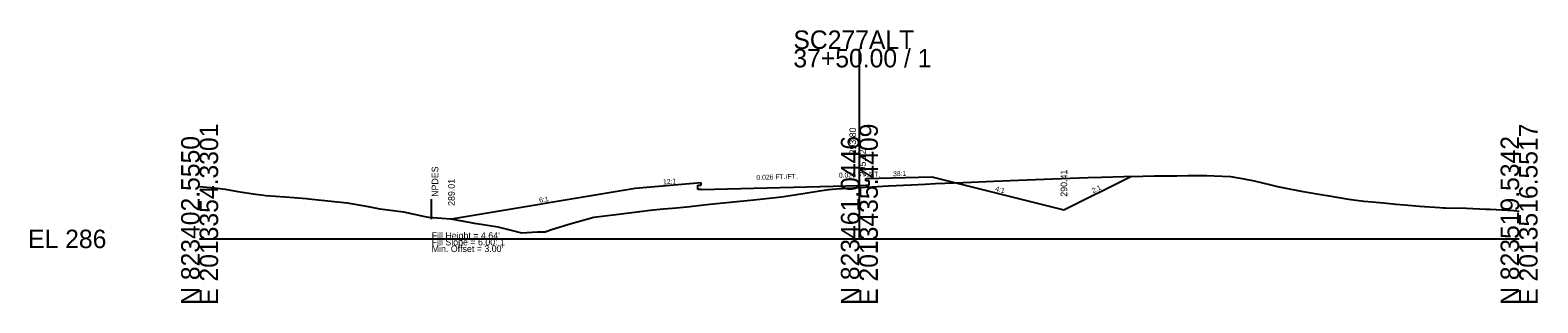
# Model space of a CAD drawing. Extents: x 205929 to 2357175, y -1785700 to 827636.
# Drawn here: x 2018394.5 to 2018623, y 825534.6 to 825575.9 of the extents above; entities that cross this region are included whole.
import ezdxf

# ---------------------------------------------------------------- set-up
doc = ezdxf.new("R2010")
doc.units = 0
for name, color, linetype in [('RD_GPK_XS_Cell', 7, 'Continuous'), ('RD_XS_Base', 7, 'Continuous'), ('RD_XS_EarthShd', 7, 'Continuous'), ('RD_XS_ExGround', 7, 'Continuous'), ('RD_XS_NPDES', 7, 'Continuous'), ('RD_XS_Pave', 7, 'Continuous'), ('RD_XS_TieSlope', 7, 'Continuous'), ('RD_XS_TX_Elev_EX', 7, 'Continuous'), ('RD_XS_TX_Elev_PR', 7, 'Continuous'), ('RD_XS_TX_ShdSlope', 7, 'Continuous'), ('RD_XS_TX_Slope', 7, 'Continuous'), ('RD_XS_TX_Warning', 7, 'Continuous')]:
    doc.layers.add(name, color=color, linetype=linetype)

msp = doc.modelspace()

# ---------------------------------------------------------------- linework, layer by layer
at = {"layer": 'RD_GPK_XS_Cell'}
for p, q in [((2018520.17, 825544.26), (2018520.17, 825573.07)), ((2018420.17, 825544.26), (2018520.17, 825544.26)), ((2018520.17, 825544.26), (2018620.17, 825544.26))]:
    msp.add_line(p, q, dxfattribs=at)
at = {"layer": 'RD_XS_Base'}
for p, q in [((2018496.17, 825551.74), (2018520.17, 825552.37)), ((2018520.17, 825552.37), (2018521.17, 825552.4))]:
    msp.add_line(p, q, dxfattribs=at)
at = {"layer": 'RD_XS_EarthShd'}
for p, q in [((2018521.17, 825553.4), (2018531.17, 825553.66)), ((2018496.17, 825552.74), (2018486.17, 825551.91))]:
    msp.add_line(p, q, dxfattribs=at)
at = {"layer": 'RD_XS_ExGround'}
msp.add_lwpolyline([(2018420.17, 825552.23), (2018422.4, 825552.01), (2018424.06, 825551.78), (2018425.98, 825551.47), (2018428.64, 825551.07), (2018429.56, 825550.93), (2018430.22, 825550.85), (2018433.14, 825550.63), (2018436.39, 825550.39), (2018436.72, 825550.34), (2018437.19, 825550.3), (2018442.55, 825549.71), (2018445.74, 825549.15), (2018447.47, 825548.82), (2018448.71, 825548.69), (2018451.05, 825548.35), (2018454.29, 825547.67), (2018454.88, 825547.56), (2018458.21, 825547.29), (2018461.04, 825546.79), (2018461.8, 825546.67), (2018462.84, 825546.5), (2018465.38, 825546.09), (2018467.21, 825545.62), (2018468.96, 825545.17), (2018471.39, 825545.35), (2018472.54, 825545.31), (2018473.37, 825545.64), (2018476.12, 825546.51), (2018479.94, 825547.57), (2018483.28, 825547.94), (2018485.7, 825548.26), (2018486.87, 825548.44), (2018488.48, 825548.6), (2018490.45, 825548.82), (2018491.86, 825548.92), (2018494.03, 825549.13), (2018497.03, 825549.46), (2018498.03, 825549.56), (2018500.61, 825549.82), (2018504.19, 825550.18), (2018505.58, 825550.34), (2018508.36, 825550.65), (2018510.36, 825550.94), (2018511.94, 825551.18), (2018514.13, 825551.53), (2018515.52, 825551.75), (2018517.16, 825551.89), (2018517.59, 825551.9), (2018518.33, 825551.94), (2018520.17, 825552.06), (2018522.07, 825552.18), (2018524.61, 825552.3), (2018528.02, 825552.47), (2018530.15, 825552.57), (2018531.72, 825552.65), (2018535.94, 825552.82), (2018540.53, 825553.01), (2018541.83, 825553.07), (2018543.04, 825553.12), (2018549.45, 825553.36), (2018554.86, 825553.57), (2018556.89, 825553.62), (2018560.26, 825553.71), (2018563.15, 825553.77), (2018564.89, 825553.82), (2018568.31, 825553.84), (2018569.98, 825553.85), (2018570.73, 825553.86), (2018571.17, 825553.86), (2018572.83, 825553.85), (2018573.97, 825553.83), (2018576.41, 825553.71), (2018578.17, 825553.43), (2018579.99, 825553.09), (2018582.52, 825552.47), (2018583.57, 825552.23), (2018584.33, 825552.08), (2018587.15, 825551.51), (2018590.73, 825550.88), (2018591.07, 825550.83), (2018594.32, 825550.27), (2018596.66, 825550), (2018597.9, 825549.86), (2018599.61, 825549.71), (2018601.48, 825549.53), (2018602.82, 825549.42), (2018605.06, 825549.23), (2018608.16, 825549.02), (2018608.64, 825548.99), (2018608.99, 825548.98), (2018612.22, 825548.93), (2018615.15, 825548.78), (2018615.81, 825548.75), (2018616.71, 825548.71), (2018619.39, 825548.55), (2018620.17, 825548.47)], dxfattribs=at)
at = {"layer": 'RD_XS_NPDES'}
msp.add_line((2018455.34, 825547.27), (2018455.34, 825550.27), dxfattribs=at)
at = {"layer": 'RD_XS_Pave'}
for p, q in [((2018495.67, 825552.4), (2018496.17, 825552.41)), ((2018495.67, 825551.73), (2018495.67, 825552.4)), ((2018496.17, 825551.74), (2018495.67, 825551.73)), ((2018496.17, 825552.41), (2018496.17, 825552.74)), ((2018521.17, 825553.07), (2018521.17, 825553.4)), ((2018521.67, 825553.08), (2018521.17, 825553.07)), ((2018521.17, 825552.4), (2018521.67, 825552.41)), ((2018521.67, 825552.41), (2018521.67, 825553.08))]:
    msp.add_line(p, q, dxfattribs=at)
at = {"layer": 'RD_XS_TieSlope'}
for p, q in [((2018531.17, 825553.66), (2018551.17, 825548.66)), ((2018551.17, 825548.66), (2018561.3, 825553.73)), ((2018486.17, 825551.91), (2018458.34, 825547.27))]:
    msp.add_line(p, q, dxfattribs=at)

# ---------------------------------------------------------------- texts
at = {"layer": 'RD_GPK_XS_Cell'}
for s, p in [('SC277ALT', (2018510.17, 825573.07)), ('37+50.00 / 1', (2018510.17, 825570.27)), ('EL 286', (2018394.17, 825542.86))]:
    msp.add_text(s, height=2.8, dxfattribs=at).set_placement(p)
for s, p in [('E 2013354.3301', (2018422.97, 825534.26)), ('E 2013435.4409', (2018522.97, 825534.26)), ('E 2013516.5517', (2018622.97, 825534.26)), ('N 823402.5550', (2018420.17, 825534.26)), ('N 823461.0446', (2018520.17, 825534.26)), ('N 823519.5342', (2018620.17, 825534.26))]:
    msp.add_text(s, height=2.8, rotation=90, dxfattribs=at).set_placement(p)
at = {"layer": 'RD_XS_TX_Elev_EX'}
msp.add_text('293.80', height=1, rotation=90, dxfattribs=at).set_placement((2018519.67, 825557.06))
at = {"layer": 'RD_XS_TX_Elev_PR'}
for s, p in [(' 295.12', (2018521.17, 825553.37)), ('290.41', (2018551.67, 825550.66)), ('289.01', (2018458.84, 825549.27))]:
    msp.add_text(s, height=1, rotation=90, dxfattribs=at).set_placement(p)
at = {"layer": 'RD_XS_TX_ShdSlope'}
for s, rotation, p in [('38:1', 1.5078, (2018525.28, 825553.76)), ('12:1', 4.7636, (2018490.44, 825552.52))]:
    msp.add_text(s, height=0.75, rotation=rotation, dxfattribs=at).set_placement(p)
at = {"layer": 'RD_XS_TX_Slope'}
for s, rotation, p in [('0.026 FT./FT.', 1.5078, (2018504.57, 825553.21)), ('0.026 FT./FT.', 1.5078, (2018517.07, 825553.54)), ('4:1', 345.9638, (2018540.72, 825551.54)), ('2:1', 26.5651, (2018555.62, 825551.17)), ('6:1', 9.4623, (2018471.69, 825549.75))]:
    msp.add_text(s, height=0.75, rotation=rotation, dxfattribs=at).set_placement(p)
at = {"layer": 'RD_XS_TX_Warning'}
msp.add_text(' NPDES', height=1, rotation=90, dxfattribs=at).set_placement((2018456.34, 825550.27))
for s, p in [("Fill Height = 4.64' ", (2018455.34, 825544.27)), ('Fill Slope = 6.00: 1', (2018455.34, 825543.27)), ("Min. Offset = 3.00' ", (2018455.34, 825542.27))]:
    msp.add_text(s, height=1, dxfattribs=at).set_placement(p)

doc.saveas('drawing.dxf')
